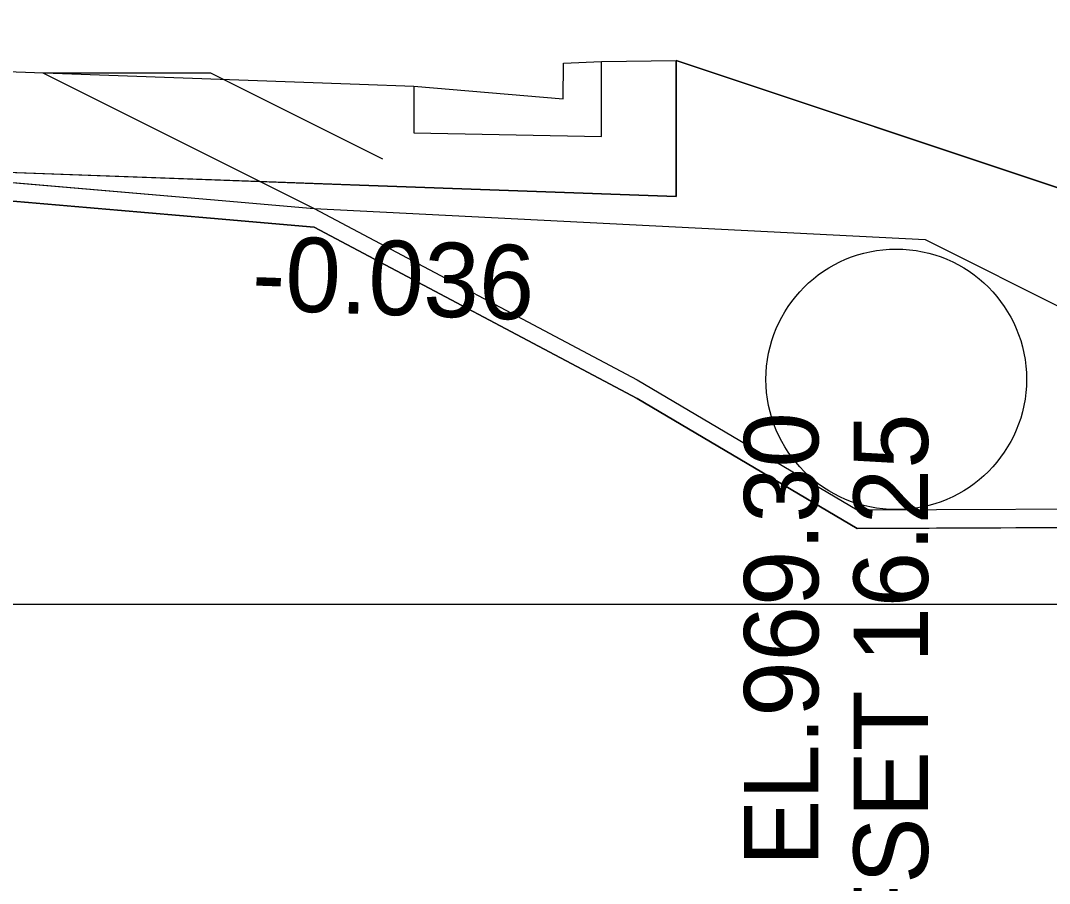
# Model space of a CAD drawing. Extents: x -192 to 2669, y -25 to 8040.
# Drawn here: x 157.45 to 171.27, y 4496.25 to 4507.84 of the extents above; entities that cross this region are included whole.
import ezdxf

# ---------------------------------------------------------------- set-up
doc = ezdxf.new("R2010")
doc.units = 0
for name, color, linetype in [('DESIGN - EARTHWORK - Shapes', 7, 'Continuous'), ('DESIGN - SCRATCH - User 2', 7, 'Continuous'), ('DESIGN - SCRATCH - User 3', 7, 'Continuous'), ('DESIGN - SHEET - Light Grid', 7, 'Continuous'), ('DESIGN - TYPICAL - Finished Grade and Subgrade', 7, 'Continuous'), ('DESIGN - TYPICAL - Subgrade Cross Slope Text', 7, 'Continuous'), ('DESIGN - TYPICAL - Subgrade Tie Text', 7, 'Continuous'), ('SURVEY - GROUND - Bottom of Topsoil Layer', 7, 'Continuous'), ('SURVEY - GROUND - Top of Ground', 7, 'Continuous')]:
    doc.layers.add(name, color=color, linetype=linetype)

msp = doc.modelspace()

# ---------------------------------------------------------------- linework, layer by layer
at = {"layer": 'DESIGN - EARTHWORK - Shapes'}
for points in [[(174.739, 4501.278), (177.369, 4502.983), (177.369, 4503.596), (166.25, 4507.302), (166.25, 4505.477), (162, 4505.63), (154.656, 4505.894), (159.999, 4505.436), (161.388, 4505.315), (165.728, 4503.014), (168.681, 4501.268), (172.94, 4501.286)], [(174.739, 4501.278), (177.369, 4502.983), (177.369, 4502.733), (174.739, 4501.028), (172.94, 4501.036), (168.681, 4501.018), (165.728, 4502.764), (161.388, 4505.065), (159.999, 4505.186), (150.832, 4505.972), (150.832, 4506.032), (154.656, 4505.894), (159.999, 4505.436), (161.388, 4505.315), (165.728, 4503.014), (168.681, 4501.268), (172.94, 4501.286)]]:
    msp.add_lwpolyline(points, close=True, dxfattribs=at)
at = {"layer": 'DESIGN - SCRATCH - User 2'}
for p, q in [((161.388, 4505.315), (169.595, 4504.897)), ((169.595, 4504.897), (177.13, 4501.129))]:
    msp.add_line(p, q, dxfattribs=at)
msp.add_circle((169.208, 4503.02), 1.75, dxfattribs=at)
at = {"layer": 'DESIGN - SCRATCH - User 3'}
for p, q in [((157.745, 4507.137), (161.388, 4505.315)), ((157.745, 4507.137), (159.995, 4507.137)), ((159.995, 4507.137), (162.307, 4505.981))]:
    msp.add_line(p, q, dxfattribs=at)
at = {"layer": 'DESIGN - SHEET - Light Grid'}
msp.add_line((150, 4500), (300, 4500), dxfattribs=at)
at = {"layer": 'DESIGN - TYPICAL - Finished Grade and Subgrade'}
for p, q in [((150, 4507.416), (162, 4506.984)), ((164.735, 4506.787), (164.74, 4507.266)), ((164.74, 4507.266), (165.25, 4507.287)), ((165.25, 4507.287), (166.25, 4507.302)), ((165.25, 4506.282), (165.25, 4507.287)), ((166.25, 4505.477), (166.25, 4507.302)), ((166.25, 4507.302), (179.763, 4502.798)), ((162, 4506.984), (162.73, 4506.957)), ((162.73, 4506.957), (164.735, 4506.787)), ((162.73, 4506.957), (162.73, 4506.332)), ((162.73, 4506.332), (165.25, 4506.282)), ((150, 4506.062), (162, 4505.63)), ((162, 4505.63), (166.25, 4505.477))]:
    msp.add_line(p, q, dxfattribs=at)
at = {"layer": 'SURVEY - GROUND - Bottom of Topsoil Layer'}
for p, q in [((150.832, 4505.972), (159.999, 4505.186)), ((159.999, 4505.186), (161.388, 4505.065)), ((161.388, 4505.065), (165.728, 4502.764)), ((165.728, 4502.764), (168.681, 4501.018)), ((168.681, 4501.018), (172.94, 4501.036))]:
    msp.add_line(p, q, dxfattribs=at)
at = {"layer": 'SURVEY - GROUND - Top of Ground'}
msp.add_lwpolyline([(123.293, 4506.243), (128.378, 4506.829), (130.774, 4507.718), (139.407, 4507.183), (140.145, 4507.145), (141.348, 4507.013), (150, 4506.291), (150.832, 4506.222), (159.999, 4505.436), (161.388, 4505.315), (165.728, 4503.014), (168.681, 4501.268), (172.94, 4501.286), (174.739, 4501.278), (179.886, 4504.613), (182.18, 4506.087), (188.546, 4506.568), (192.652, 4506.857), (203.556, 4507.725), (205.433, 4507.744), (226.001, 4507.839)], dxfattribs=at)

# ---------------------------------------------------------------- texts
at = {"layer": 'DESIGN - TYPICAL - Subgrade Cross Slope Text'}
msp.add_text('-0.036', height=1, rotation=357.9382, dxfattribs=at).set_placement((160.542, 4503.952))
at = {"layer": 'DESIGN - TYPICAL - Subgrade Tie Text'}
for s, p in [('EL.969.30', (168.163, 4496.481)), ('OFFSET 16.25', (169.634, 4493.569))]:
    msp.add_text(s, height=1, rotation=90, dxfattribs=at).set_placement(p)

doc.saveas('drawing.dxf')
